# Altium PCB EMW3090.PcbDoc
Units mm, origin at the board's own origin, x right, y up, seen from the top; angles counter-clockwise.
Board outline 18 x 33 mm, 2 copper layers (Top Layer, Bottom Layer), stack 0.171 mm thick; 41 components, 33 nets, 161 pads, 28 vias.
Unrouted connection lines stored in the file: 83.
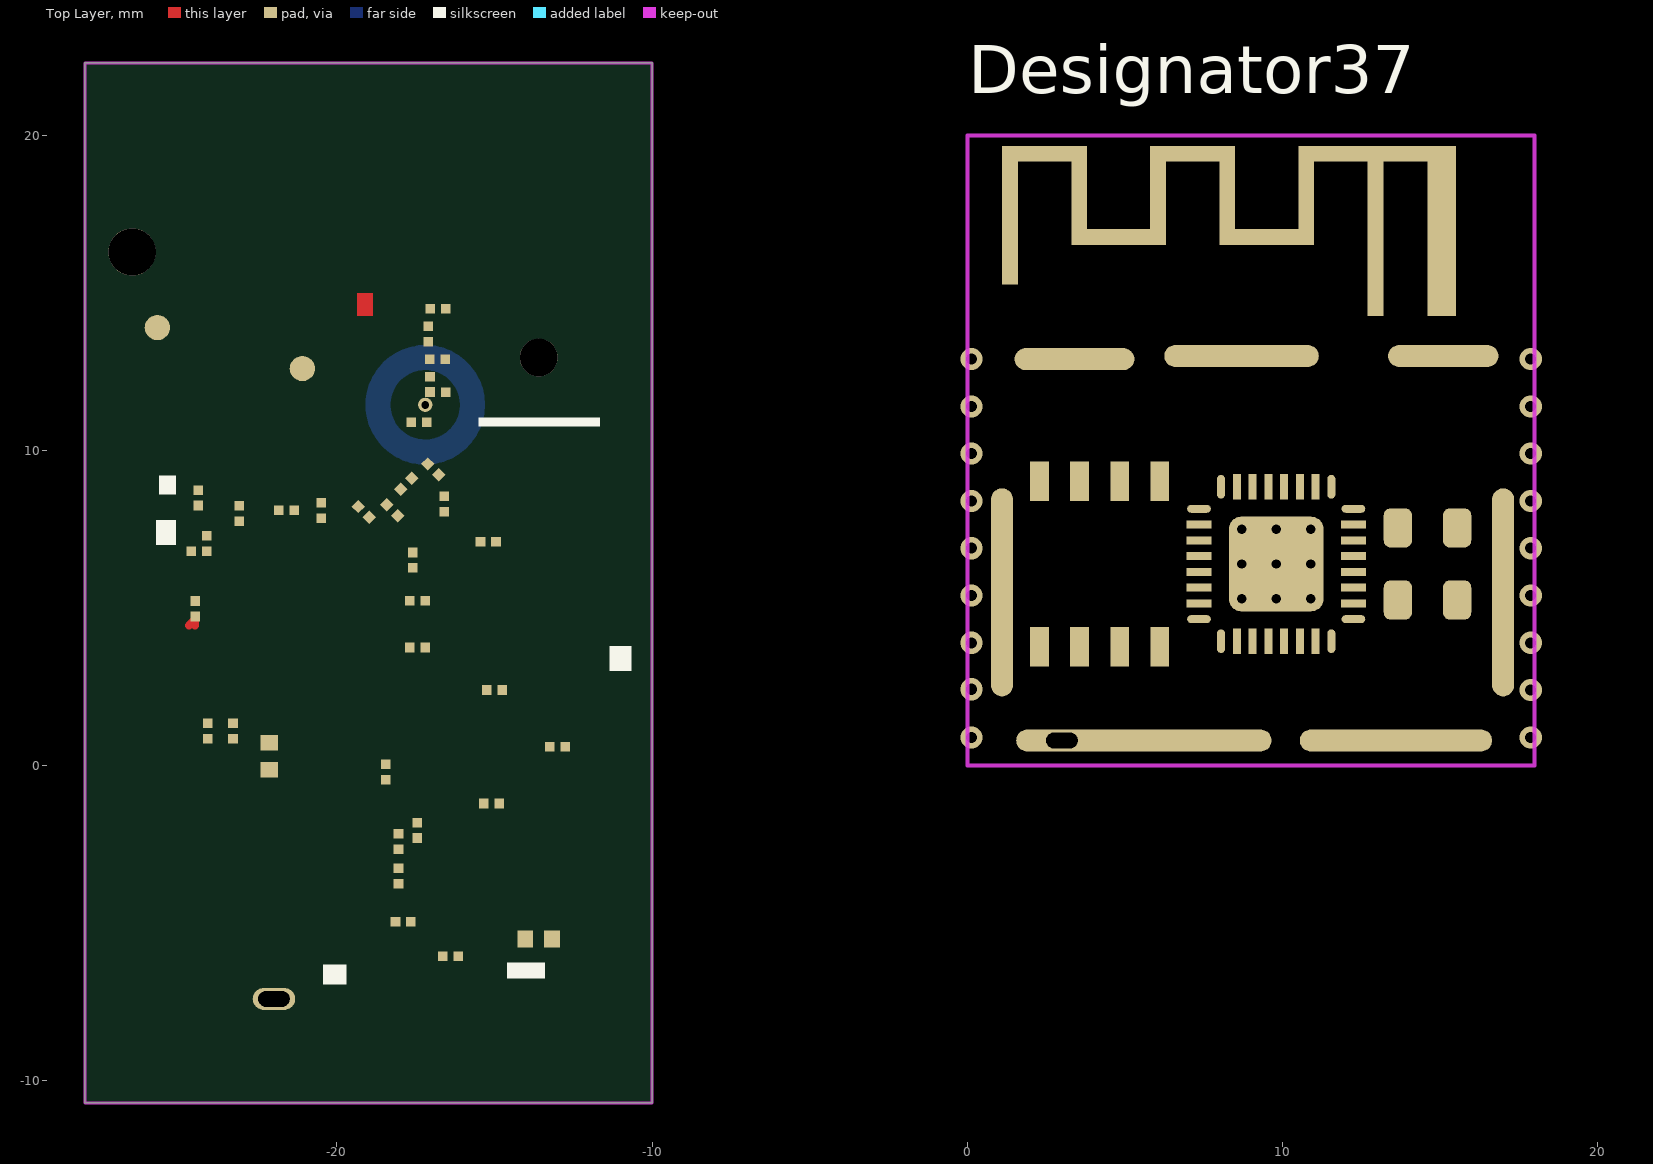
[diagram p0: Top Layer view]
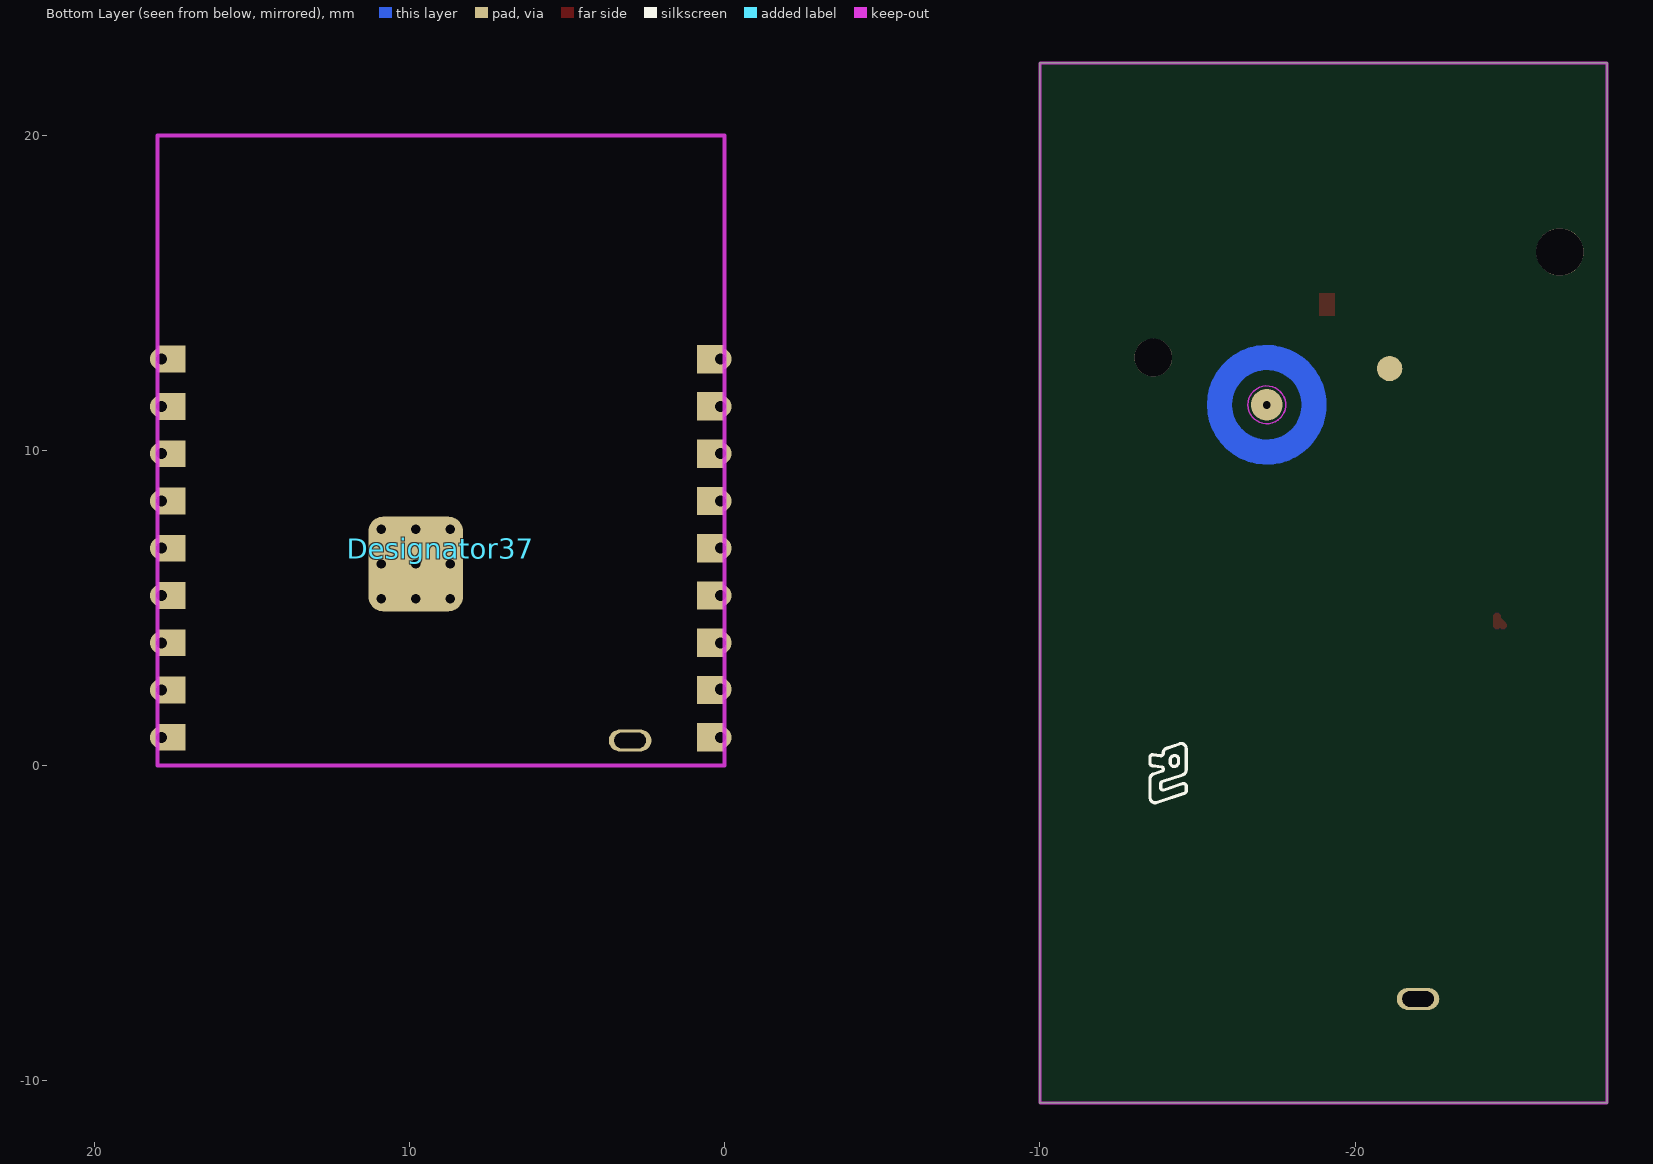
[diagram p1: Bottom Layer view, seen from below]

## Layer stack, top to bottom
Top Solder: solder mask 0.0102, Solder Resist, Dk 3.5
Top Layer: signal copper 0.0356
Dielectric1: core 0.1, FR-4, Dk 4.2
Bottom Layer: signal copper 0.0356
Bottom Solder: solder mask 0.0102, Solder Resist, Dk 3.5

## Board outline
-28,-10.7 -28,22.3 -10,22.3 -10,-10.7

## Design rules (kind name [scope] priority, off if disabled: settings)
Clearance [All] p1: gap=0.127
ComponentClearance [All] p1: gap=0.051 collisioncheckmode=3 verticalgap=0.051 showdistances=FALSE
HoleToHoleClearance [All] p1: gap=0.152 allowstackedmicrovias=TRUE
MinimumSolderMaskSliver [All] p1: minsoldermaskwidth=0.102
PlaneClearance [All] p1: clearance=0.127
PlaneConnect [All] p1: planeconnectstyle=Direct reliefexpansion=0.508 reliefentries=4 reliefconductorwidth=0.254 reliefairgap=0.254
PolygonConnect [All] p1: connectstyle=Direct reliefconductorwidth=0.254 reliefentries=4 polygonreliefangle="90 Angle" airgapwidth=0.254
RoutingVias [All] p1: holewidth=0.2 width=0.5 viastyle="Through Hole" minholewidth=0.2 minwidth=0.406 maxholewidth=0.5 maxwidth=1.2
SilkToSilkClearance [All] p1: silktosilkclearance=0
SilkToSolderMaskClearance [IsPad] p1: minsilkscreentomaskgap=0 clearancetoexposedcopper=TRUE
SolderMaskExpansion [All] p1: expansion=0
Width [All] p1: maxlimit=1.27 minlimit=0.102 preferedwidth=0.254 toplayer_prefwidth=0.152 bottomlayer_minwidth=0.152 minimp=50.000000 maximp=50.000000 favimp=50.000000
23 further rules are at their usual default settings.

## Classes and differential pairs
component class "Components Class 1": " "
component class EMW3080: A1 C1 C2 C3 C4 C5 C6 C8 C10 C12 C16 C17 C18 C19 C20 C26 C51 CON1 J1 L1 L2 L3 L8 R1 R3 R5 R6 R7 R8 R9 R11 R12 S1 U1 U2 U3 Y1

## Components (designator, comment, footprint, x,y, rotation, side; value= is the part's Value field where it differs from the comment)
Designator37 "Comment" PCBComponent_1 0,0 r0 top
U1 "" QFN-32 9.8,6.4 r180 top
U2 "" SOP8-150MIL 4.2,6.4 r90 top
? "" "S ANT" 12.95,14.55 r180 top locked
? "" R0201 -24.5,4.98 r270 top
? "" R0201 -24.375,6.805 r180 top
? "" R0201 -21.6,8.1 r0 top
? "" C0201 -24.4,8.5 r90 top
? "" R0201 -24.13,7.05 r90 top
? "" C0201 -23.1,8 r90 top
? "" R0201 -17.45,-2.05 r90 top
? "" L0201 -17.4,10.9 r0 top
? "" C0201 -16.4,-6.05 r0 top
? "" R0201 -18.45,-0.2 r90 top
? "" R0201 -15.1,-1.2 r0 top
? "" R0201 -18.05,-3.5 r90 top
? "" R0201 -17.9,-4.95 r0 top
? "" C0201 -17.45,3.75 r0 top
? "" C0201 -15,2.4 r0 top
? "" C0201 -15.2,7.1 r0 top
? "" C0201 -17.05,12.1 r90 top
? "" C0201 -16.8,11.85 r0 top
? "" L0201 -19.15,8.05 r135 top
? "" L0201 -17.1,13.7 r270 top
? "" C0201 -18.25,8.1 r135 top
? "" C0201 -17.8,8.95 r45 top
? "" C0201 -16.95,9.4 r135 top
? "" C0201 -16.81,12.9 r0 top
? "" C0201 -16.8,14.5 r0 top
? "" "CS325 24.000M" 14.6,6.4 r90 top
? "" C0201 -17.45,5.23 r0 top
? "" R0201 -16.6,8.3 r90 top
? "" C0402 -13.6,-5.5 r0 top
? "" AR-TP -17.2,11.45 r0 top
? "" C0201 -17.6,6.52 r90 top
? "" C0201 -20.5,8.1 r90 top
? "" R0201 -13,0.6 r0 top
? "" C0402 -22.15,0.3 r270 top
? "" C0201 -23.3,1.1 r90 top
? "" C0201 -24.1,1.1 r90 top
? "" C0201 -18.05,-2.4 r90 top

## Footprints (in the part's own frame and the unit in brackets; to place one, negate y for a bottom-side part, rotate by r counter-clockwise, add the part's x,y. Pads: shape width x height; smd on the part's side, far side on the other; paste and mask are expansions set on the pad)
AR-TP [mm]
  round 0.45 / inner round 0.45 / far side round 1 hole 0.25 mask+0.05: 1(0,0)
  Bottom Layer circle w0.8: c0,0 r1.5
C0201 [mm]
  rect 0.305x0.305 smd mask+0.05: 1(-0.245,0) 2(0.245,0)
C0402 [mm]
  rect 0.5x0.55 smd mask+0.05: 1(-0.425,0) 2(0.425,0)
"CS325 24.000M" [mm] "CITIZEN AT-CUT CRYSTAL UNIT"
  rrect50% 1.25x0.9 smd mask+0.05: 1(-1.143,-0.94) 2(1.143,-0.94) 3(1.143,0.94) 4(-1.143,0.94)
L0201 [mm]
  rect 0.305x0.305 smd mask+0.05: 1(-0.245,0) 2(0.245,0)
PCBComponent_1 [mm]
  rect 0.85x0.9 smd far side: 1(0.45,12.9) 2(0.45,11.4) 3(0.45,9.9) 4(0.45,8.4) 5(0.45,6.9) 6(0.45,5.4) 7(0.45,3.9) 8(0.45,2.4) 9(0.45,0.9)
  rect 0.9x0.85 smd far side: 10(17.55,0.9) 11(17.55,2.4) 12(17.55,3.9) 13(17.55,5.4) 14(17.55,6.9) 15(17.55,8.4) 16(17.55,9.9) 17(17.55,11.4) 18(17.55,12.9)
  Keep-Out Layer lines w0.127: 0,0 0,20 18,20 18,0 0,0
QFN-32 [mm] "QFN, 32-Leads, Body 5.00x5.00mm, Pitch 0.50mm, Thermal Pad 3.50x3.50mm, IPC High Density"
  oval 0.75x0.25 smd mask+0.05: 1(-2.45,1.75) 8(-2.45,-1.75) 17(2.45,-1.75) 24(2.45,1.75)
  rect 0.8x0.25 smd mask+0.05: 2(-2.45,1.25) 3(-2.45,0.75) 4(-2.45,0.25) 5(-2.45,-0.25) 6(-2.45,-0.75) 7(-2.45,-1.25) 18(2.45,-1.25) 19(2.45,-0.75) 20(2.45,-0.25) 21(2.45,0.25) 22(2.45,0.75) 23(2.45,1.25)
  oval 0.25x0.75 smd mask+0.05: 9(-1.75,-2.45) 16(1.75,-2.45) 25(1.75,2.45) 32(-1.75,2.45)
  rect 0.25x0.8 smd mask+0.05: 10(-1.25,-2.45) 11(-0.75,-2.45) 12(-0.25,-2.45) 13(0.25,-2.45) 14(0.75,-2.45) 15(1.25,-2.45) 26(1.25,2.45) 27(0.75,2.45) 28(0.25,2.45) 29(-0.25,2.45) 30(-0.75,2.45) 31(-1.25,2.45)
  rrect25% 3x3 smd mask+0.05: 33(0,0)
  rrect30% 3x3 smd far side mask+0.05: 33(0,0)
R0201 [mm]
  rect 0.305x0.305 smd mask+0.05: 1(-0.245,0) 2(0.245,0)
"S ANT" [mm]
  rect 0.5x5.4 smd paste+0: 1(0,-2.413)
  rect 4.1x0.5 smd paste+0: 1(0.4,-4.863)
  rect 0.5x3.14 smd paste+0: 1(2.2,-3.543) 1(4.7,-3.543) 1(6.9,-3.543) 1(9.4,-3.543)
  rect 3x0.5 smd paste+0: 1(3.45,-2.223) 1(8.15,-2.223)
  rect 2.7x0.5 smd paste+0: 1(5.8,-4.863) 1(10.5,-4.863)
  rect 0.5x4.4 smd paste+0: 1(11.6,-2.913)
  rect 0.9x5.4 smd paste+0: 2(-2.1,-2.413)
SOP8-150MIL [mm] "SOP, 8-Leads, Body 4.90x3.90mm, Pitch 1.27mm, IPC High Density"
  rect 1.25x0.6 smd mask+0.05: 1(-2.625,1.905) 2(-2.625,0.635) 3(-2.625,-0.635) 4(-2.625,-1.905) 5(2.625,-1.905) 6(2.625,-0.635) 7(2.625,0.635) 8(2.625,1.905)

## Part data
U1: library part RTL8710BN, "Realtek 2.4G WiFi SoC"
U2: library part W25Q80BV
?: library part CRYS_24MHz_CS325, "Crystal 24MHz"

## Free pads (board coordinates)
  oval 1.35x0.7 hole 0.5 slot 1 at 0 deg mask+0.05: 0(-22,-7.4) 0(3,0.8)
  round 0.8 smd mask+0.05: 1(-25.7,13.9) 1(-21.1,12.6)
  round 0.8 smd far side mask+0.05: 1(-21.1,12.6)
  oval 0.7x6.6 smd mask+0.05: 1(1.1,5.5) 1(17,5.5)
  oval 3.8x0.7 smd mask+0.05: 1(3.4,12.9)
  oval 8.1x0.7 smd mask+0.05: 1(5.6,0.8)
  oval 4.9x0.7 smd mask+0.05: 1(8.7,13)
  oval 6.1x0.7 smd mask+0.05: 1(13.6,0.8)
  oval 3.5x0.7 smd mask+0.05: 1(15.1,13)
  round 1.5 hole 1.5 unplated mask+0.05: ""(-26.5,16.3)
  round 1.2 hole 1.2 unplated mask+0.05: ""(-13.6,12.95)

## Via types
v1: diameter 0.7, hole 0.35, Top Layer to Bottom Layer, tented both sides, 19 vias
v2: diameter 0.6, hole 0.3, Top Layer to Bottom Layer, 9 vias

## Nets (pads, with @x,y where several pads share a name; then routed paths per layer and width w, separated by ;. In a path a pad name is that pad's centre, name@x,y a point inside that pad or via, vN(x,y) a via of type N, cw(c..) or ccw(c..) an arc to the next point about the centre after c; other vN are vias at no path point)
CHIP_EN: ?.1@-21.845,8.1 ?.1@-24.4,8.255 U1.12
DEBUG_RXD: U1.2
DEBUG_TXD: ?.2@-12.755,0.6 U1.1
DGND: ?.1@-15.245,2.4 ?.1@-16.6,8.055 ?.1@-16.645,-6.05 ?.1@-17.645,10.9 ?.1@-18.077,7.927 ?.1@-23.3,0.855 ?.1@-24.1,0.855 ?.2@15.54,7.543 ?.2@-13.175,-5.5 ?.2@-14.955,7.1 ?.2@-16.555,14.5 ?.2@-16.565,12.9 ?.2@-17.6,6.765 ?.2@-17.205,3.75 ?.2@-17.205,5.23 ?.2@-18.05,-2.155 ?.2@-19.323,8.223 ?.2@-20.5,8.345 ?.2@-22.15,-0.125 ?.2@-23.1,8.245 ?.2@-24.4,8.745 ?.2@-24.13,7.295 ?.4 pad.0 pad.1@1.1,5.5 pad.1@3.4,12.9 pad.1@5.6,0.8 pad.1@8.7,13 pad.1@13.6,0.8 U1.7 U1.33 U2.4
  other v2: 8.7,5.3 9.8,5.3 10.9,5.3 8.7,6.4 9.8,6.4 10.9,6.4 8.7,7.5 9.8,7.5 10.9,7.5
GPIOA_8: U1.20
GPIOA_11: U1.23
HD#: ?.1@-18.05,-3.745 U2.7
I2C0_SCL: ?.1@-18.45,-0.445 U1.31
I2C0_SDA: ?.1@-15.345,-1.2 U1.30
NetC1_1: ?.1@15.54,5.257 ?.1@-15.445,7.1 U1.5
NetC2_1: ?.2@-14.755,2.4 ?.3 U1.4
PWM2: ?.1@-24.13,6.805 U1.16
PWM3: U1.17
PWM4: U1.28
QSPI_CLK: U1.22 U2.6
QSPI_D0: U1.21 U2.5
QSPI_D1: U1.19 U2.2
QSPI_SS#: ?.1@-24.5,5.225 U1.18 U2.1
REST#: ?.2@-17.45,-1.805
RFIO: ?.2@-18.423,8.273 U1.9
RFO1: ?.1@-17.055,12.9 ?.2@-17.1,13.455 ?.2@-17.05,12.345
RFO2: ?.1@-17.2,11.45 ?.2@-17.627,9.123
RFO3: ?.2@-16.555,11.85
RFO5: ?.1@-16.777,9.227 ?.2@-16.6,8.545
RFO6: 
SWD_CLK: U1.13
SWD_DIO: U1.14
UART0_RXD: U1.29
UART0_TXD: U1.32
VBEAT_MEAS: U1.27
VD12: ?.1@-22.15,0.725 ?.1@-23.1,7.755 ?.2@-24.62,6.805 U1.15 U1.26
VD33: ?.1@-13.245,0.6 ?.1@-14.025,-5.5 ?.1@-17.6,6.275 ?.1@-17.45,-2.295 ?.1@-17.695,3.75 ?.1@-17.695,5.23 ?.1@-18.05,-2.645 ?.1@-20.5,7.855 ?.2@-14.855,-1.2 ?.2@-16.155,-6.05 ?.2@-17.655,-4.95 ?.2@-18.05,-3.255 ?.2@-18.45,0.045 ?.2@-21.355,8.1 ?.2@-23.3,1.345 ?.2@-24.1,1.345 U1.3 U1.6 U1.8 U1.10 U1.11 U1.24 U1.25 U2.8 | length 0.6
  Top Layer w0.254: -24.7,4.45 -24.5,4.65 ; -24.5,4.45 -24.5,4.735
WP#: ?.1@-18.145,-4.95 U2.3
pads on no net: ?.1@1.35,17.463 ?.1@2.45,19.413 ?.1@3.55,18.093 ?.1@4.8,16.773 ?.1@6.05,18.093 ?.1@7.15,19.413 ?.1@8.25,18.093 ?.1@9.5,16.773 ?.1@10.75,18.093 ?.1@12.55,19.413 ?.1@12.95,16.963 ?.1@-17.1,13.945 ?.1@-17.05,11.855 ?.1@-17.045,11.85 ?.1@-17.045,14.5 ?.1@-17.973,8.777 ?.1@-18.977,7.877 ?.2@15.05,16.963 ?.2@-17.123,9.573 ?.2@-17.155,10.9 ?.2@-24.5,4.735 Designator37.1 Designator37.2 Designator37.3 Designator37.4 Designator37.5 Designator37.6 Designator37.7 Designator37.8 Designator37.9 Designator37.10 Designator37.11 Designator37.12 Designator37.13 Designator37.14 Designator37.15 Designator37.16 Designator37.17 Designator37.18
copper on no net:
  other v1: 0.125,0.9 0.125,0.9 17.875,0.9 17.875,2.4 0.125,2.425 0.125,3.9 17.875,3.9 0.125,5.4 17.875,5.4 0.125,6.9 17.875,6.9 0.125,8.4 17.875,8.4 0.125,9.9 17.875,9.9 0.125,11.4 17.875,11.4 0.125,12.9 17.875,12.9

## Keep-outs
Bottom Layer:
  circle w0.05: c-17.2,11.45 r0.6
Keep-Out Layer:
  lines w0.1: -28,-10.7 -28,22.3 -10,22.3 -10,-10.7 -28,-10.7
  lines w0.125: 0,0 0,20 18,20 18,0 0,0
  text "EMW3080(K)" at 6.4,-2 h0.76

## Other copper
Top Layer:
  region net DGND: -19.36,15 -19.36,14.27 -18.85,14.27 -18.85,15

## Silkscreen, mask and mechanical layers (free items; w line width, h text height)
Top Overlay:
  region: -14.6,-6.25 -14.6,-6.75 -13.4,-6.75 -13.4,-6.25
  region: -20.45,-6.3 -20.45,-6.95 -19.7,-6.95 -19.7,-6.3
  region: -25.75,7.8 -25.75,7 -25.1,7 -25.1,7.8
  region: -25.65,9.2 -25.65,8.6 -25.1,8.6 -25.1,9.2
  region: -15.505,11.05 -15.505,10.76 -11.66,10.76 -11.66,11.05
  region: -15.505,11.05 -15.505,10.76 -11.66,10.76 -11.66,11.05
  region: -11.35,3.8 -11.35,3 -10.65,3 -10.65,3.8
Bottom Overlay:
  lines w0.102: -14.644,-0.799 ccw(c-14.564,-0.799) -14.589,-0.875 -13.708,-1.168 ccw(c-13.658,-1.017) -13.498,-1.017 -13.498,-0.412 ccw(c-13.658,-0.412) -13.607,-0.26 -13.885,-0.168 cw(c-13.873,-0.13) -13.913,-0.13 -13.913,-0.086 cw(c-13.873,-0.086) -13.879,-0.047 -13.566,0 ccw(c-13.578,0.079) -13.498,0.079 -13.498,0.27 ccw(c-13.578,0.27) -13.589,0.349 -13.825,0.314 cw(c-13.837,0.394) -13.917,0.394 -13.917,0.403 ccw(c-14.077,0.403) -14.024,0.554 -14.431,0.695 ccw(c-14.484,0.544) -14.644,0.544 -14.644,-0.139 ccw(c-14.484,-0.139) -14.534,-0.291 -13.889,-0.506 cw(c-13.914,-0.582) -13.834,-0.582 -13.834,-0.696 cw(c-13.914,-0.696) -13.939,-0.771 -14.538,-0.572 ccw(c-14.564,-0.648) -14.644,-0.648 -14.644,-0.799 ; -14.401,0.104 ccw(c-14.281,0.104) -14.319,-0.01 -14.296,-0.017 ccw(c-14.258,0.097) -14.138,0.097 -14.138,0.193 ccw(c-14.258,0.193) -14.219,0.307 -14.242,0.315 ccw(c-14.281,0.201) -14.401,0.201 -14.401,0.104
